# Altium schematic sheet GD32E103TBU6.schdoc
size 127 x 101 mm
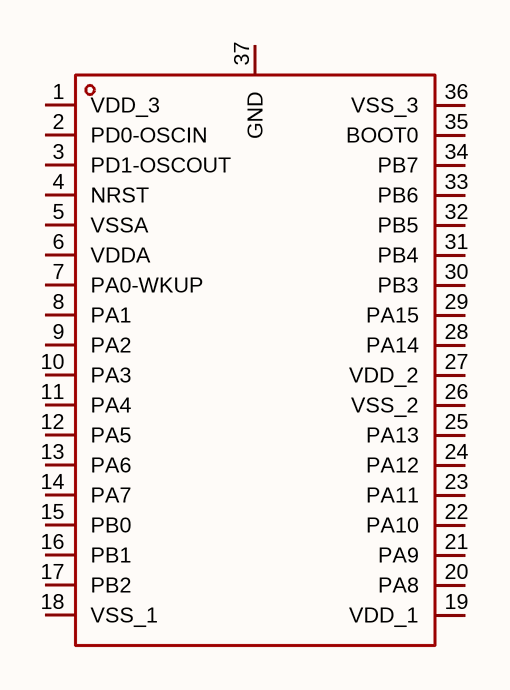
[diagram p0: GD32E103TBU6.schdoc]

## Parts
U?  gd32e103tbu6  [QFN-36_L6.0-W6.0-P0.50-BL-EP3.9]  (value not drawn)

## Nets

Not connected (* = marked no-connect by the designer): U? 1(VDD_3) 2(PD0-OSCIN) 3(PD1-OSCOUT) 4(NRST) 5(VSSA) 6(VDDA) 7(PA0-WKUP) 8(PA1) 9(PA2) 10(PA3) 11(PA4) 12(PA5) 13(PA6) 14(PA7) 15(PB0) 16(PB1) 17(PB2) 18(VSS_1) 19(VDD_1) 20(PA8) 21(PA9) 22(PA10) 23(PA11) 24(PA12) 25(PA13) 26(VSS_2) 27(VDD_2) 28(PA14) 29(PA15) 30(PB3) 31(PB4) 32(PB5) 33(PB6) 34(PB7) 35(BOOT0) 36(VSS_3) 37(GND)

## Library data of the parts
U? = gd32e103tbu6: CPU内核:ARM-M4;CPU最大主频:120MHz;应用领域:-;; Manufacturer: GigaDevice(兆易创新); AddInBom: yes; ModelId: b1ed419fd36e4725a7c7e2ff93c037c5; ModelTransform: 237.007,237.007,0,0,0,0,0,0,0; CPU Core: ARM-M4; CPU Maximum Speed: 120MHz; Program Storage Size: 128KB; Program Memory Type: FLASH; Number of I/O: 80; ADC (Bit): 12bit; Voltage - Supply: 1.71V~3.6V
